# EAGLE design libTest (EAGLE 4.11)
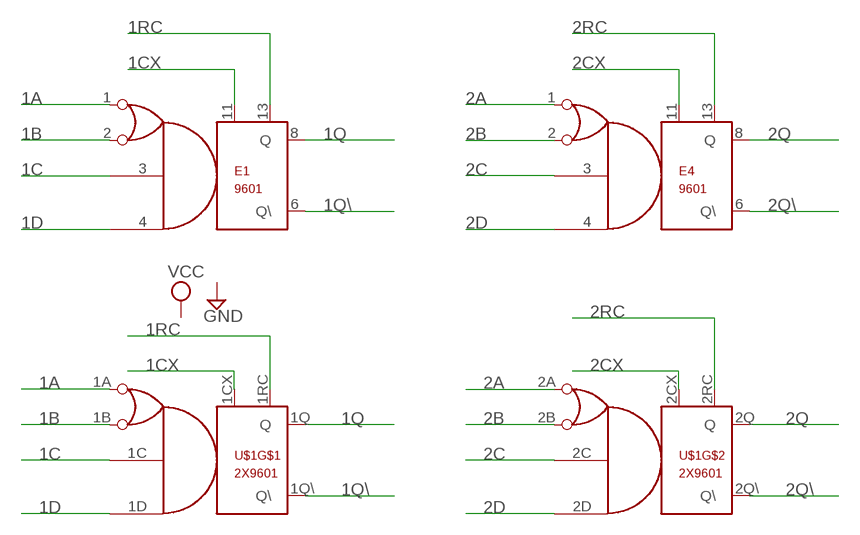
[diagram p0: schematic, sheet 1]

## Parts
E1  9601  9601DEC  [DIL14]
E4  9601  9601DEC  [DIL14]
U$1  2X9601  [EXPERIMENTAL]

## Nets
1A: E1.1 U$1.1A
1B: E1.2 U$1.1B
1C: E1.3 U$1.1C
1CX: E1.11 U$1.1CX
1D: E1.4 U$1.1D
1Q: E1.8(Q) U$1.1Q(Q)
1Q\: E1.6(Q\) U$1.1Q\(Q\)
1RC: E1.13 U$1.1RC
2A: E4.1 U$1.2A
2B: E4.2 U$1.2B
2C: E4.3 U$1.2C
2CX: E4.11 U$1.2CX
2D: E4.4 U$1.2D
2Q: E4.8(Q) U$1.2Q(Q)
2Q\: E4.6(Q\) U$1.2Q\(Q\)
2RC: E4.13 U$1.2RC

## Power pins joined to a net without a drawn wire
GND: E1.7(GND) E4.7(GND) U$1.8(GND)
VCC: E1.14(VCC) E4.14(VCC) U$1.16(VCC)

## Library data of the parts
E1 E4 = dec-con:9601
U$1 = dec-con:2X9601

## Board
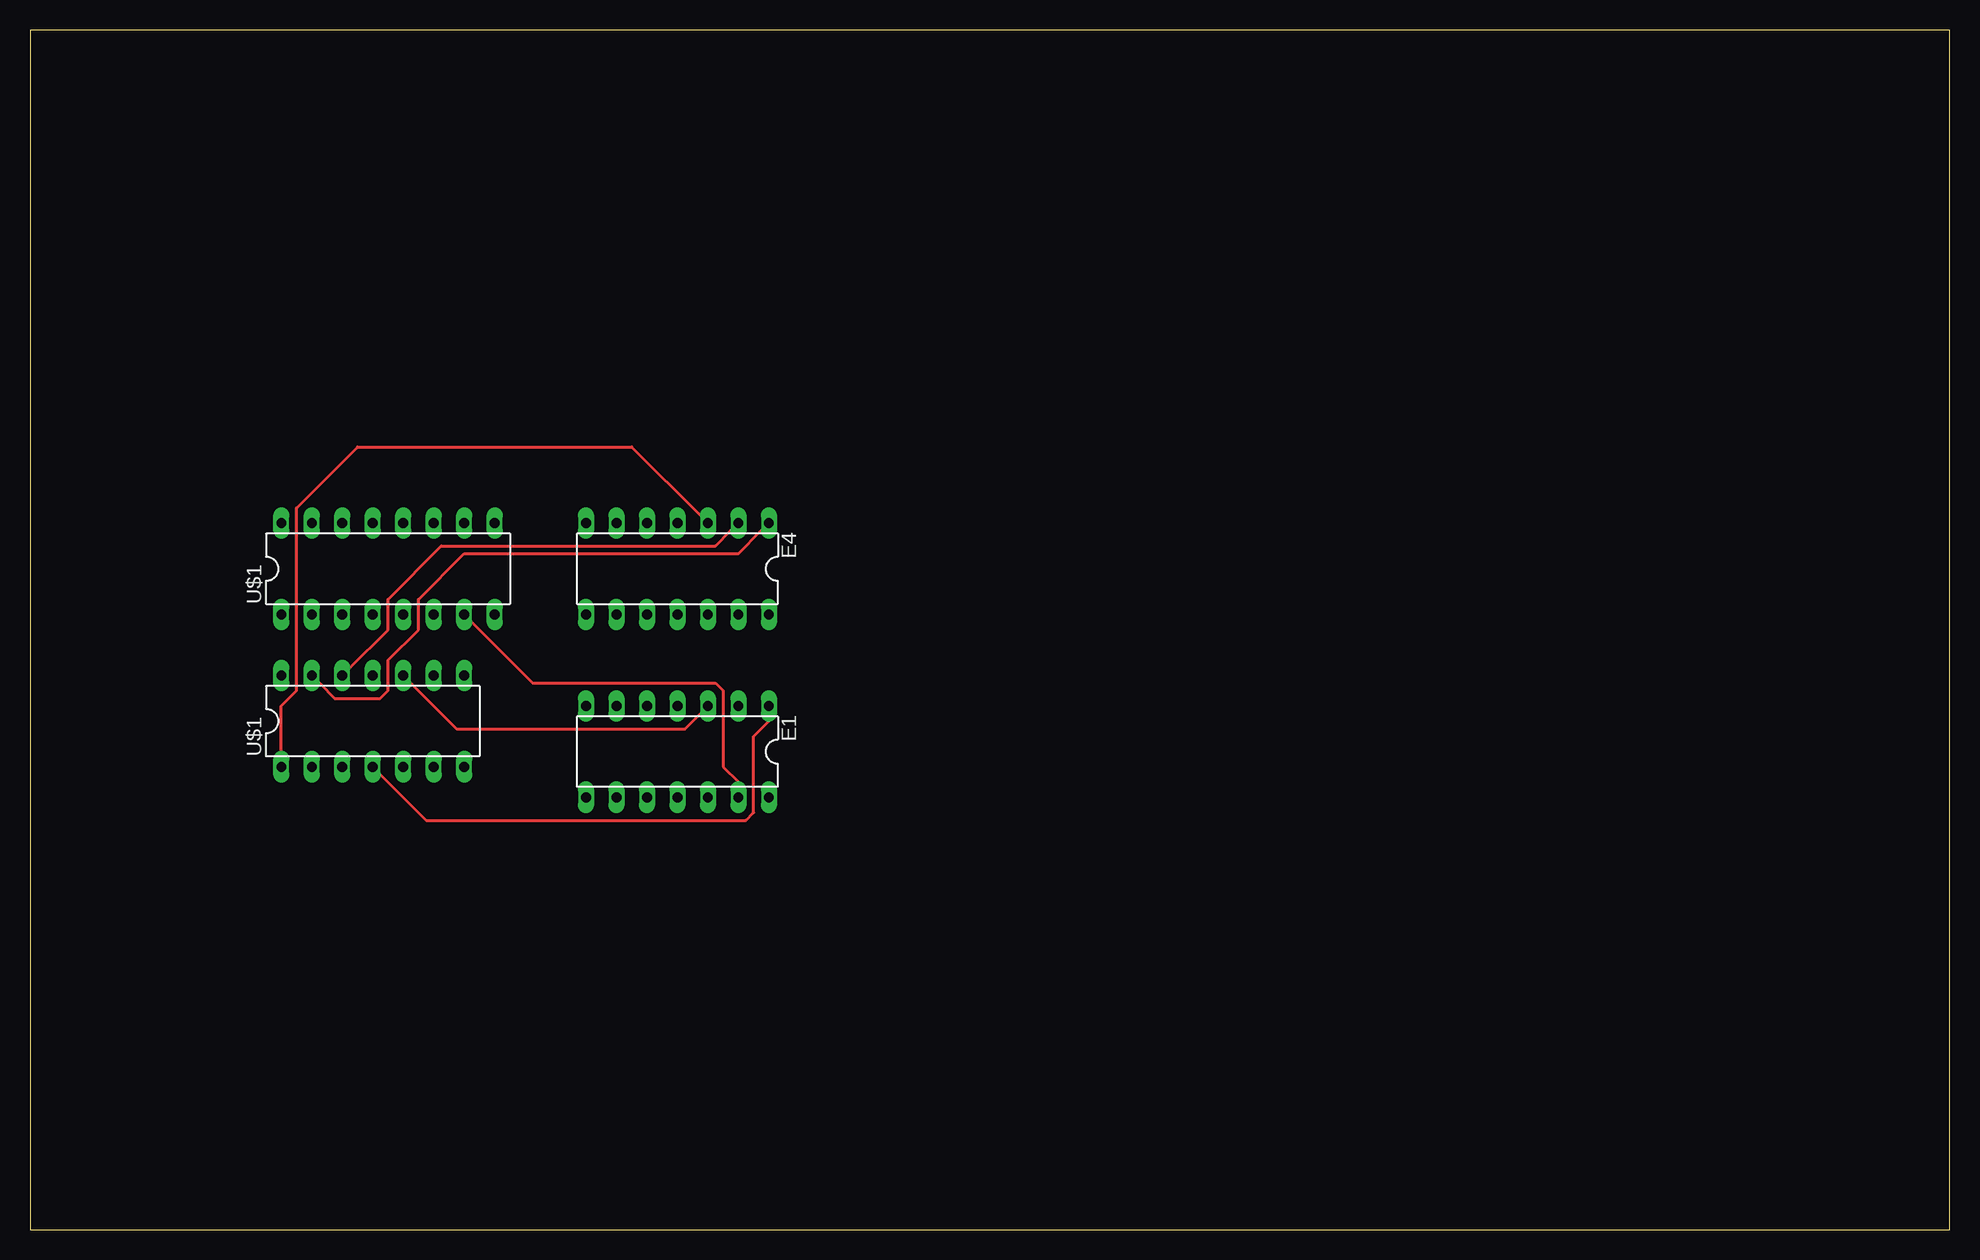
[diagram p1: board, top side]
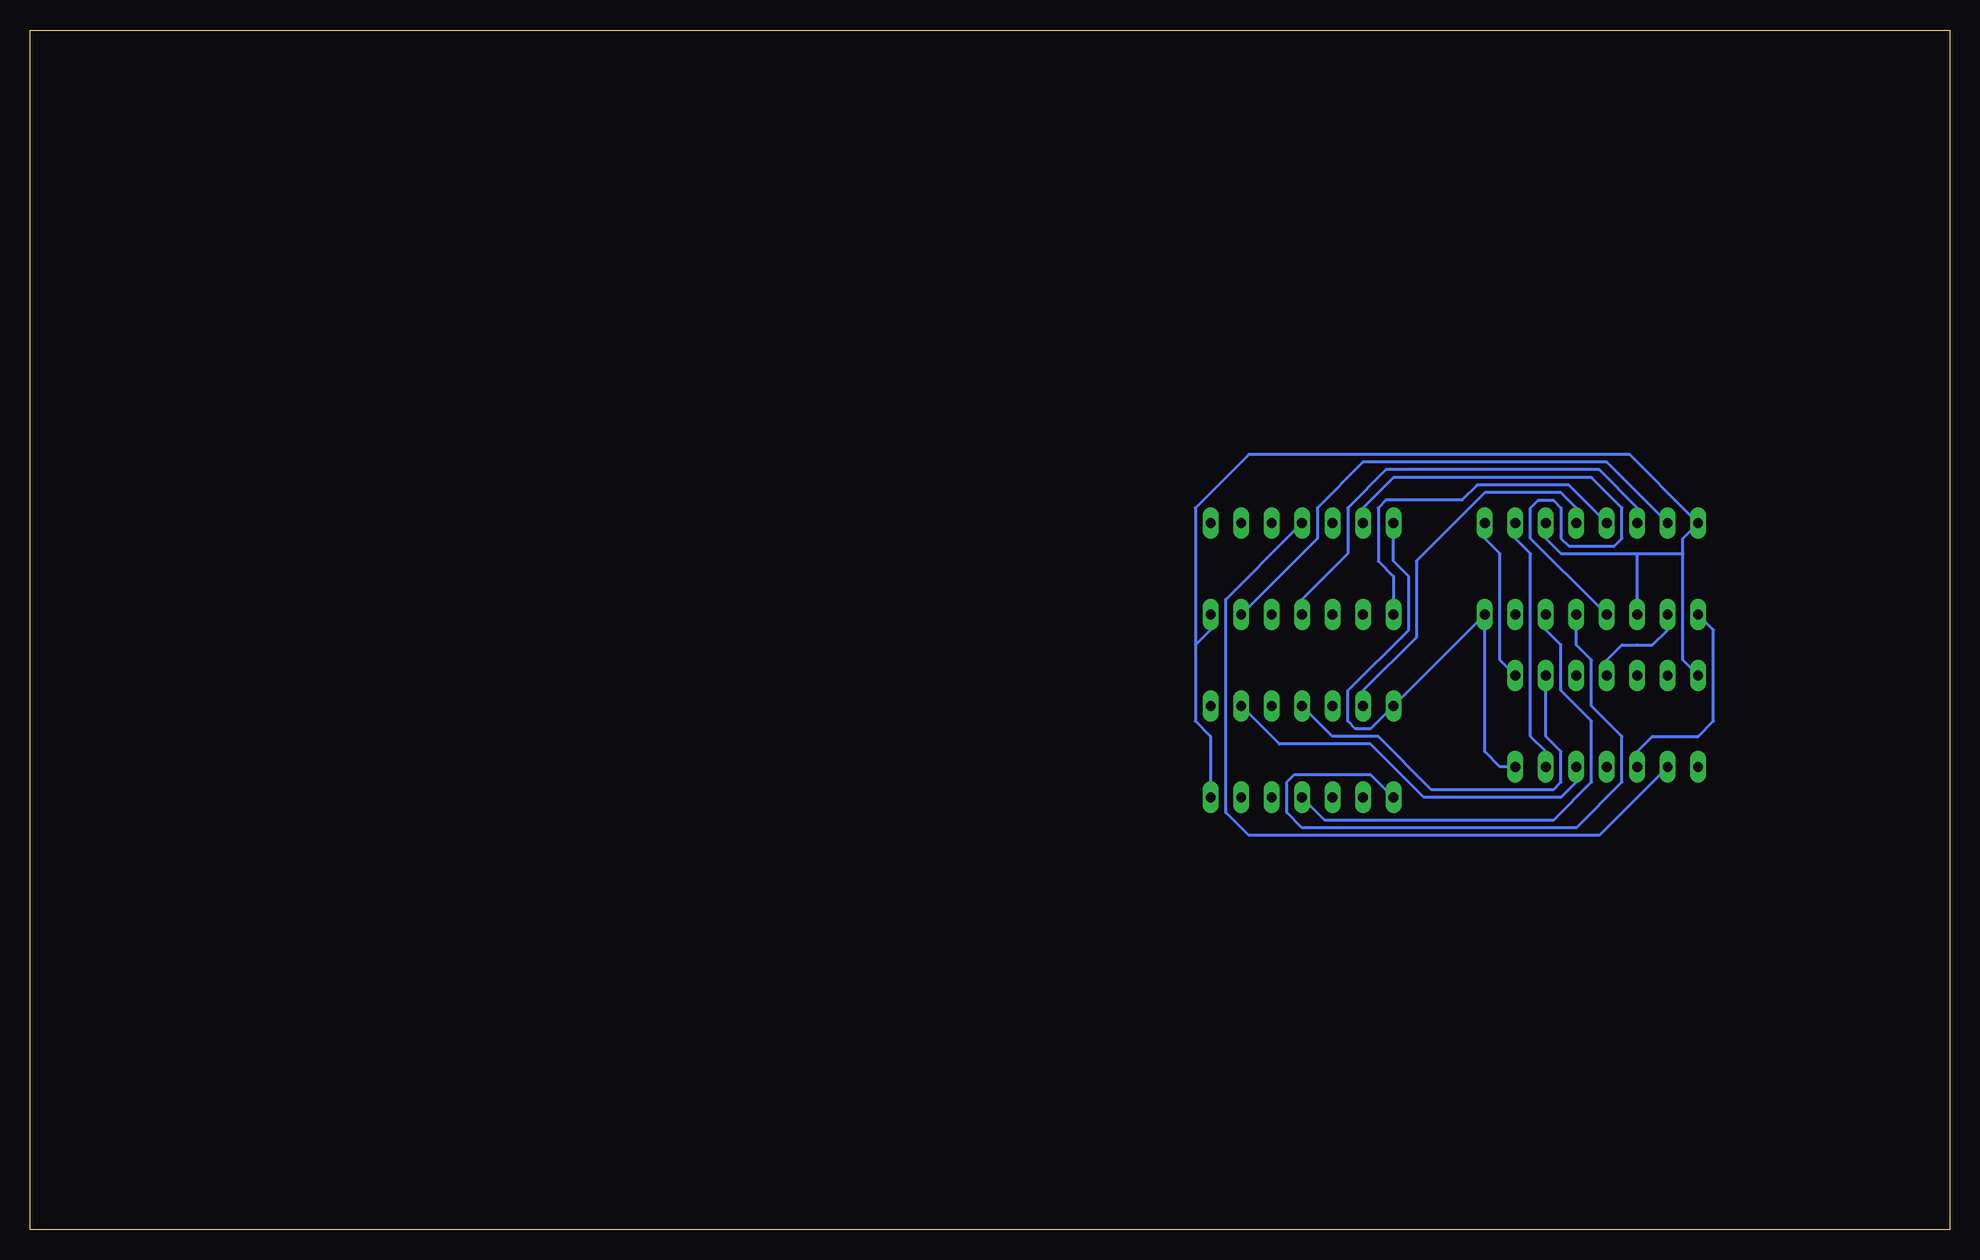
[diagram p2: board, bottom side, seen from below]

Size 160 x 100 mm. Coordinates in mm from the lower left corner, seen from the top.
Outline: 0,0 160,0 160,100 0,100 0,0
Copper layers (1*16): Top 0.035mm / dielectric 1.5mm / Bottom 0.035mm
Design rules "olimex10mil": minimum track width 10mil, minimum drill 24mil, track to track 10mil, track to pad 10mil, pad to pad 10mil, via to via 10mil, smd to smd 10mil, copper to edge 40mil, drill to drill 10mil, minimum pad ring 10mil, minimum via ring 8mil, stop-mask expansion 0mil, vias tented up to drill 0mil, thermal gap 10mil

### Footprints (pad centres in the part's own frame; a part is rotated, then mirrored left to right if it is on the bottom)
DIL14 = drill 0.813 long: 1 -7.62,-3.81; 2 -5.08,-3.81; 3 -2.54,-3.81; 4 0,-3.81; 5 2.54,-3.81; 6 5.08,-3.81; 7 7.62,-3.81; 8 7.62,3.81; 9 5.08,3.81; 10 2.54,3.81; 11 0,3.81; 12 -2.54,3.81; 13 -5.08,3.81; 14 -7.62,3.81
EXPERIMENTAL = drill 0.813 long: 1 -8.89,2.54; 1A -1.27,-10.16; 1B 1.27,-10.16; 1C 1.27,-2.54; 1CX 3.81,2.54; 1D 3.81,-2.54; 1Q 1.27,2.54; 1Q\ 1.27,10.16; 1RC 6.35,2.54; 2 -6.35,2.54; 2A -6.35,-2.54; 2B -3.81,-2.54; 2C -8.89,-10.16; 2CX -3.81,10.16; 2D -6.35,-10.16; 2Q -1.27,10.16; 2Q\ -1.27,2.54; 2RC -6.35,10.16; 3 -3.81,2.54; 8 8.89,2.54; 9 8.89,10.16; 10 6.35,10.16; 11 3.81,10.16; 16 -8.89,10.16; 21 6.35,-10.16; 23 -3.81,-10.16; 25 3.81,-10.16; 28 6.35,-2.54; 31 -1.27,-2.54; 34 -8.89,-2.54

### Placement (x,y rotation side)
E1  53.97,39.84 180 top
E4  53.97,55.08 180 top
U$1  29.84,48.73 0 top

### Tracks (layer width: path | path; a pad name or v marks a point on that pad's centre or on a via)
1A
  Top 0.254: U$1.1A 29.2,37.94 33.02,34.12 59.69,34.12 60.32,34.76 60.32,41.11 61.59,42.38 E1.1
1B
  Bottom 0.254: U$1.1B 31.11,37.3 32.38,36.03 43.81,36.03 48.26,40.48 55.88,40.48 58.41,43.02 E1.2
1C
  Top 0.254: U$1.1C 31.74,45.55 35.55,41.74 54.61,41.74 55.88,43.02 E1.3
1CX
  Bottom 0.254: E1.11 53.34,35.39 52.07,34.12 33.02,34.12 29.84,37.3 29.84,42.38 32.38,44.92 32.38,48.73 33.65,50 U$1.1CX
1D
  Bottom 0.254: U$1.1D 33.65,44.92 33.65,41.11 32.38,39.84 32.38,37.3 33.02,36.66 43.18,36.66 47.62,41.11 51.43,41.11 53.34,43.02 E1.4
1Q
  Bottom 0.254: U$1.1Q 31.11,50 31.11,48.73 29.84,47.46 29.84,43.65 27.3,41.11 27.3,37.3 31.11,33.49 53.97,33.49 55.24,34.76 55.24,37.3 54.61,37.94 48.26,37.94 46.98,36.66 E1.8
1Q\
  Bottom 0.254: U$1.1Q\ 31.11,60.16 32.38,61.43 38.73,61.43 44.45,55.71 44.45,49.37 48.89,44.92 E1.6
1RC
  Top 0.254: U$1.1RC 36.83,50.63 41.91,45.55 57.15,45.55 57.78,44.92 57.78,38.57 59.05,37.3 E1.13
2A
  Top 0.254: U$1.2A 24.12,45.55 25.39,44.28 29.2,44.28 29.84,44.92 29.84,47.46 32.38,50 32.38,52.54 36.19,56.35 59.05,56.35 60.96,58.25 E4.1
2B
  Top 0.254: U$1.2B 26.66,46.82 29.84,50 29.84,52.54 34.29,56.98 57.15,56.98 58.41,58.25 E4.2
2C
  Top 0.254: U$1.2C 20.95,39.84 20.95,43.65 22.22,44.92 22.22,60.16 27.3,65.24 50.16,65.24 55.88,59.52 E4.3
2CX
  Bottom 0.254: U$1.2CX 26.03,60.16 29.2,63.34 46.98,63.34 50.16,60.16 50.16,56.35 53.97,52.54 E4.11
2D
  Bottom 0.254: U$1.2D 24.12,37.94 29.2,32.85 58.41,32.85 60.32,34.76 60.32,52.54 54.61,58.25 E4.4
2Q
  Bottom 0.254: E4.8 46.35,52.54 46.35,54.45 47.62,55.71 47.62,60.16 46.98,60.8 40.64,60.8 39.37,62.06 31.74,62.06 29.2,59.52 U$1.2Q
2Q\
  Bottom 0.254: U$1.2Q\ 29.2,51.91 34.92,57.62 34.92,60.16 34.29,60.8 33.02,60.8 32.38,60.16 32.38,57.62 31.74,56.98 27.93,56.98 27.3,57.62 27.3,60.16 29.84,62.7 46.35,62.7 48.89,60.16 E4.6
2RC
  Bottom 0.254: U$1.2RC 24.12,59.52 28.57,63.97 48.89,63.97 52.7,60.16 52.7,57.62 58.41,51.91 E4.13
GND
  Bottom 0.254: U$1.8 39.37,50.63 45.72,44.28 E1.7 46.98,43.02 48.26,41.74 49.53,41.74 50.16,42.38 50.16,44.92 45.08,50 45.08,54.45 46.35,55.71 46.35,57.62 E4.7
VCC
  Bottom 0.254: 62.86,48.73 62.86,42.38 61.59,41.11 61.59,37.3 E1.14 | 62.86,48.73 61.59,50 E4.14 | 62.86,48.73 62.86,60.16 58.41,64.61 26.66,64.61 21.58,59.52 U$1.16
